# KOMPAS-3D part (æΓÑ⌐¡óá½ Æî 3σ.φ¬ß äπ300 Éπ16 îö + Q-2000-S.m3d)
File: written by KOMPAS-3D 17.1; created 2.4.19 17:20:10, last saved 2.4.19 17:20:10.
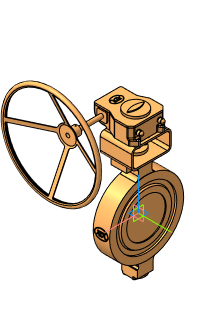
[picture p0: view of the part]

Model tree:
1. Операция без истории:1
